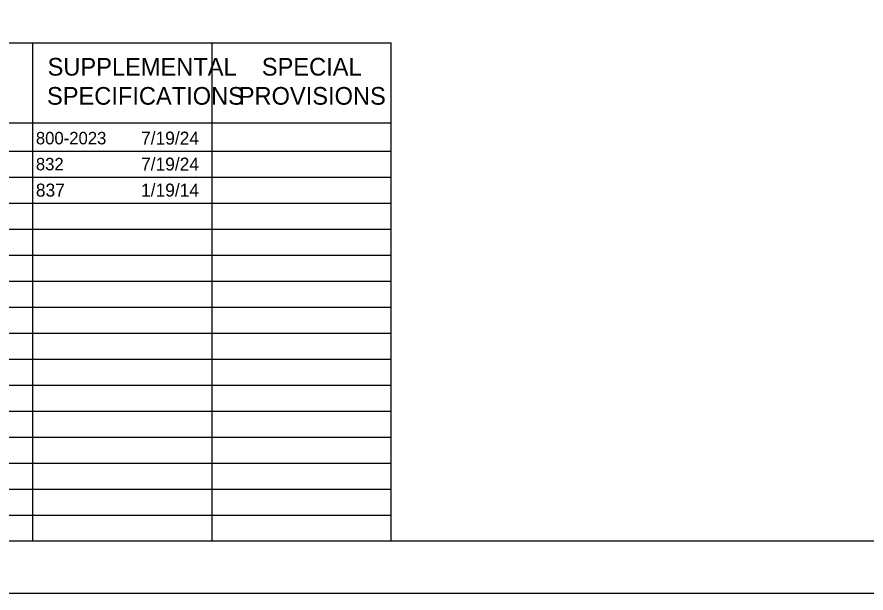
# Model space of a CAD drawing. Extents: x -2.1 to 31.9, y 6.3 to 28.3.
# Drawn here: x 17.93 to 26.1, y 6.34 to 11.88 of the extents above; entities that cross this region are included whole.
import ezdxf

# ---------------------------------------------------------------- set-up
doc = ezdxf.new("R2010")
doc.units = 0
for name, color, linetype in [('SH_Border', 7, 'Continuous'), ('SH_Cut_Line', 7, 'Continuous'), ('SH_Data', 7, 'Continuous'), ('SH_Text', 7, 'Continuous'), ('TX_P_1', 7, 'Continuous')]:
    doc.layers.add(name, color=color, linetype=linetype)

msp = doc.modelspace()

# ---------------------------------------------------------------- linework, layer by layer
at = {"layer": 'SH_Border'}
msp.add_lwpolyline([(-0.5656, 27.844), (31.4344, 27.844), (31.4344, 6.844), (-0.5656, 6.844)], close=True, dxfattribs=at)
at = {"layer": 'SH_Cut_Line'}
msp.add_lwpolyline([(-2.0656, 6.344), (31.9344, 6.344), (31.9344, 28.344), (-2.0656, 28.344)], close=True, dxfattribs=at)
at = {"layer": 'SH_Data'}
for p, q in [((8.0844, 11.6357), (21.5344, 11.6357)), ((18.0844, 6.844), (18.0844, 11.6357)), ((19.8094, 6.844), (19.8094, 11.6357)), ((21.5344, 6.844), (21.5344, 11.6357)), ((8.0844, 10.8649), (21.5344, 10.8649)), ((8.0844, 10.594), (21.5344, 10.594)), ((8.0844, 10.344), (21.5344, 10.344)), ((8.0844, 10.094), (21.5344, 10.094)), ((8.0844, 9.844), (21.5344, 9.844)), ((8.0844, 9.594), (21.5344, 9.594)), ((8.0844, 9.344), (21.5344, 9.344)), ((8.0844, 9.094), (21.5344, 9.094)), ((8.0844, 8.844), (21.5344, 8.844)), ((8.0844, 8.594), (21.5344, 8.594)), ((8.0844, 8.344), (21.5344, 8.344)), ((8.0844, 8.094), (21.5344, 8.094)), ((8.0844, 7.844), (21.5344, 7.844)), ((8.0844, 7.594), (21.5344, 7.594)), ((8.0844, 7.344), (21.5344, 7.344)), ((8.0844, 7.094), (21.5344, 7.094))]:
    msp.add_line(p, q, dxfattribs=at)

# ---------------------------------------------------------------- texts
at = {"layer": 'SH_Text'}
for s, height, p in [('SUPPLEMENTAL', 0.17, (18.227, 11.3203)), ('SPECIAL', 0.17, (20.2886, 11.3203)), ('SPECIFICATIONS', 0.17, (18.2215, 11.0403)), ('PROVISIONS', 0.17, (20.0667, 11.0403)), ('800-2023', 0.12, (18.1144, 10.659)), ('832', 0.12, (18.1144, 10.409))]:
    msp.add_text(s, height=height, dxfattribs=at).set_placement(p)
at = {"layer": 'TX_P_1'}
for s, p in [('7/19/24', (19.1265, 10.6565)), ('7/19/24', (19.1265, 10.4065)), ('837', (18.1144, 10.1565)), ('1/19/14', (19.1265, 10.1565))]:
    msp.add_text(s, height=0.125, dxfattribs=at).set_placement(p)

doc.saveas('drawing.dxf')
